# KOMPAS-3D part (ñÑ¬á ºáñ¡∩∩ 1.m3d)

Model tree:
1. Эскиз:1
2. Операция выдавливания:1
     Расстояние 1 = 0.6
3. Эскиз:2
4. Вырезать элемент выдавливания:1
     Толщина стенки 1 = 3; Толщина стенки 2 = 3; Расстояние 1 = 10
5. Эскиз:3
6. Вырезать элемент выдавливания:2
     Толщина стенки 1 = 3; Толщина стенки 2 = 3; Расстояние 1 = 10
7. Эскиз:4
8. Вырезать элемент выдавливания:3
     Толщина стенки 1 = 3; Толщина стенки 2 = 3; Расстояние 1 = 10
9. Эскиз:5
10. Вырезать элемент выдавливания:4
     Толщина стенки 1 = 3; Толщина стенки 2 = 3; Расстояние 1 = 10
